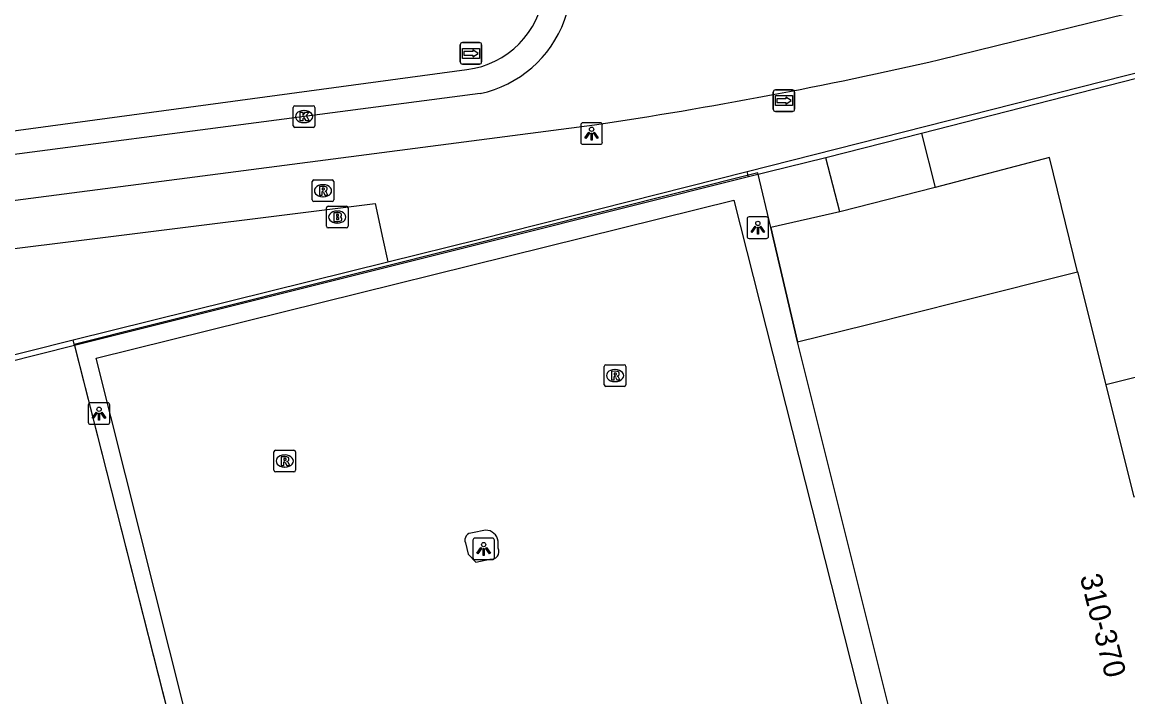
# Model space of a CAD drawing. Extents: x 160806 to 161707, y 383697 to 384148.
# Drawn here: x 160905.1 to 160956.3, y 383728.8 to 383760.1 of the extents above; entities that cross this region are included whole.
import ezdxf

# ---------------------------------------------------------------- set-up
doc = ezdxf.new("R2010")
doc.units = 0
for name, color, linetype in [('IMGEO_Brandkraan', 7, 'Continuous'), ('IMGEO_Dek', 7, 'Continuous'), ('IMGEO_Fietspad_open', 7, 'Continuous'), ('IMGEO_Kolk', 7, 'Continuous'), ('IMGEO_Lichtpunt', 7, 'Continuous'), ('IMGEO_Muur', 7, 'Continuous'), ('IMGEO_Pand', 7, 'Continuous'), ('IMGEO_Pand_nummerreeks', 7, 'Continuous'), ('IMGEO_Pand_overbouw', 7, 'Continuous'), ('IMGEO_Parkeervlak_gesloten', 7, 'Continuous'), ('IMGEO_Parkeervlak_open', 7, 'Continuous'), ('IMGEO_Rioolput', 7, 'Continuous'), ('IMGEO_Voetpad_gesloten', 7, 'Continuous'), ('IMGEO_Voetpad_open', 7, 'Continuous'), ('IMGEO_Wegwijzer', 7, 'Continuous')]:
    doc.layers.add(name, color=color, linetype=linetype)

msp = doc.modelspace()

# ---------------------------------------------------------------- linework, layer by layer
at = {"layer": 'IMGEO_Brandkraan'}
for p, q in [((160919.175, 383750.595), (160919.175, 383751.447)), ((160919.25, 383751.521), (160920.102, 383751.521)), ((160919.663, 383751.301), (160919.688, 383751.301)), ((160920.176, 383751.447), (160920.176, 383750.595)), ((160919.686, 383750.741), (160919.661, 383750.741)), ((160920.102, 383750.521), (160919.25, 383750.521))]:
    msp.add_line(p, q, dxfattribs=at)
for points in [[(160919.175, 383750.595), (160919.175, 383751.447)], [(160919.25, 383751.521), (160920.102, 383751.521)], [(160919.523, 383751.221), (160919.523, 383750.821), (160919.736, 383750.821)], [(160919.754, 383751.221), (160919.523, 383751.221)], [(160920.176, 383751.447), (160920.176, 383750.595)], [(160919.702, 383751.14), (160919.648, 383751.14), (160919.648, 383751.064)], [(160919.648, 383751.064), (160919.701, 383751.064)], [(160919.71, 383750.988), (160919.648, 383750.988), (160919.648, 383750.907)], [(160919.648, 383750.907), (160919.71, 383750.907)], [(160920.102, 383750.521), (160919.25, 383750.521)]]:
    msp.add_lwpolyline(points, dxfattribs=at)
for centre, radius, start, end in [((160919.252, 383751.445), 0.0765, 91.552, 178.448), ((160919.252, 383751.445), 0.0765, 91.552, 178.448), ((160919.758, 383751.076), 0.145, 59.4692, 91.5367), ((160919.783, 383751.123), 0.0922, 285.5137, 58.1501), ((160920.1, 383751.445), 0.0765, 1.552, 88.448), ((160920.1, 383751.445), 0.0765, 1.552, 88.448), ((160919.703, 383751.102), 0.0379, 267.8285, 90.9355), ((160919.711, 383750.947), 0.0404, 269.8759, 90.5077), ((160919.742, 383751.072), 0.251, 268.6676, 293.5347), ((160919.788, 383750.931), 0.105, 301.3115, 78.989), ((160919.252, 383750.597), 0.0765, 181.552, 268.448), ((160919.252, 383750.597), 0.0765, 181.552, 268.448), ((160920.1, 383750.597), 0.0765, 271.552, 358.448), ((160920.1, 383750.597), 0.0765, 271.552, 358.448)]:
    msp.add_arc(centre, radius, start, end, dxfattribs=at)
for centre, major_axis, ratio, start_param, end_param in [((160919.662, 383751.021), (-0.387, 0.002), 0.722429, 4.712389, 7.853982), ((160919.687, 383751.021), (-0.39, 0.002), 0.717154, 1.570796, 4.712389)]:
    msp.add_ellipse(centre, major_axis=major_axis, ratio=ratio, start_param=start_param, end_param=end_param, dxfattribs=at)
at = {"layer": 'IMGEO_Dek'}
msp.add_lwpolyline([(160965.894, 383710.159), (160949.913, 383709.678), (160949.497, 383711.315), (160949.382, 383711.774), (160941.019, 383745.231), (160939.898, 383750), (160939.772, 383750.534), (160939.177, 383753.065), (160907.479, 383745.104), (160918.048, 383703.574), (160983.268, 383705.804)], dxfattribs=at)
at = {"layer": 'IMGEO_Fietspad_open'}
for points in [[(160947.606, 383758.324), (160957.999, 383760.873), (160958.651, 383761.038), (160960.089, 383761.401), (160969.85, 383763.865), (160970.809, 383764.107), (160986.327, 383768.025), (161022.896, 383777.258), (161039.914, 383781.555), (161040.772, 383781.738)], [(160926.307, 383756.75), (160894.194, 383752.541)], [(160894.884, 383750.529), (160931.609, 383755.303)]]:
    msp.add_lwpolyline(points, dxfattribs=at)
for centre, radius, start, end in [((160925.172, 383761.997), 5.368, 282.2012, 37.6103), ((160901.535, 383958.42), 205.331, 278.42229, 282.9662)]:
    msp.add_arc(centre, radius, start, end, dxfattribs=at)
at = {"layer": 'IMGEO_Kolk'}
for p, q in [((160917.637, 383755.254), (160917.637, 383756.106)), ((160917.712, 383756.18), (160918.564, 383756.18)), ((160918.125, 383755.96), (160918.15, 383755.96)), ((160918.638, 383756.106), (160918.638, 383755.254)), ((160918.148, 383755.4), (160918.123, 383755.4)), ((160918.564, 383755.18), (160917.712, 383755.18))]:
    msp.add_line(p, q, dxfattribs=at)
for points in [[(160917.637, 383755.254), (160917.637, 383756.106)], [(160917.712, 383756.18), (160918.564, 383756.18)], [(160917.958, 383755.88), (160918.081, 383755.88), (160918.081, 383755.729), (160918.211, 383755.88), (160918.375, 383755.88), (160918.229, 383755.729), (160918.382, 383755.48), (160918.23, 383755.48), (160918.145, 383755.644), (160918.081, 383755.577), (160918.081, 383755.48), (160917.958, 383755.48), (160917.958, 383755.88)], [(160918.638, 383756.106), (160918.638, 383755.254)], [(160918.564, 383755.18), (160917.712, 383755.18)]]:
    msp.add_lwpolyline(points, dxfattribs=at)
for centre, start, end in [((160917.714, 383756.104), 91.552, 178.448), ((160917.714, 383756.104), 91.552, 178.448), ((160918.562, 383756.104), 1.552, 88.448), ((160918.562, 383756.104), 1.552, 88.448), ((160917.714, 383755.256), 181.552, 268.448), ((160917.714, 383755.256), 181.552, 268.448), ((160918.562, 383755.256), 271.552, 358.448), ((160918.562, 383755.256), 271.552, 358.448)]:
    msp.add_arc(centre, 0.0765, start, end, dxfattribs=at)
for centre, major_axis, ratio, start_param, end_param in [((160918.124, 383755.68), (-0.387, 0.002), 0.722429, 4.712389, 7.853982), ((160918.149, 383755.68), (-0.39, 0.002), 0.717154, 1.570796, 4.712389)]:
    msp.add_ellipse(centre, major_axis=major_axis, ratio=ratio, start_param=start_param, end_param=end_param, dxfattribs=at)
at = {"layer": 'IMGEO_Lichtpunt'}
for p, q in [((160930.97, 383755.297), (160930.97, 383754.49)), ((160930.97, 383755.297), (160930.97, 383754.49)), ((160931.872, 383755.392), (160931.064, 383755.392)), ((160931.872, 383755.392), (160931.064, 383755.392)), ((160931.966, 383754.49), (160931.966, 383755.297)), ((160931.966, 383754.49), (160931.966, 383755.297)), ((160931.064, 383754.396), (160931.872, 383754.396)), ((160931.064, 383754.396), (160931.872, 383754.396)), ((160938.677, 383750.931), (160938.677, 383750.124)), ((160938.677, 383750.931), (160938.677, 383750.124)), ((160939.579, 383751.026), (160938.771, 383751.026)), ((160939.579, 383751.026), (160938.771, 383751.026)), ((160939.673, 383750.124), (160939.673, 383750.931)), ((160939.673, 383750.124), (160939.673, 383750.931)), ((160938.771, 383750.03), (160939.579, 383750.03)), ((160938.771, 383750.03), (160939.579, 383750.03)), ((160908.135, 383742.312), (160908.135, 383741.505)), ((160908.135, 383742.312), (160908.135, 383741.505)), ((160909.037, 383742.407), (160908.229, 383742.407)), ((160909.037, 383742.407), (160908.229, 383742.407)), ((160909.131, 383741.505), (160909.131, 383742.312)), ((160909.131, 383741.505), (160909.131, 383742.312)), ((160908.229, 383741.411), (160909.037, 383741.411)), ((160908.229, 383741.411), (160909.037, 383741.411)), ((160925.965, 383736.034), (160925.965, 383735.227)), ((160925.965, 383736.034), (160925.965, 383735.227)), ((160926.867, 383736.129), (160926.059, 383736.129)), ((160926.867, 383736.129), (160926.059, 383736.129)), ((160926.961, 383735.227), (160926.961, 383736.034)), ((160926.961, 383735.227), (160926.961, 383736.034)), ((160926.059, 383735.133), (160926.867, 383735.133)), ((160926.059, 383735.133), (160926.867, 383735.133))]:
    msp.add_line(p, q, dxfattribs=at)
for points in [[(160931.344, 383754.961), (160931.383, 383754.933), (160931.195, 383754.671), (160931.157, 383754.698), (160931.344, 383754.961)], [(160931.446, 383754.913), (160931.493, 383754.913), (160931.493, 383754.591), (160931.446, 383754.591), (160931.446, 383754.913)], [(160931.556, 383754.933), (160931.594, 383754.96), (160931.781, 383754.698), (160931.742, 383754.67), (160931.556, 383754.933)], [(160939.051, 383750.595), (160939.09, 383750.567), (160938.902, 383750.305), (160938.864, 383750.332), (160939.051, 383750.595)], [(160939.153, 383750.547), (160939.2, 383750.547), (160939.2, 383750.225), (160939.153, 383750.225), (160939.153, 383750.547)], [(160939.263, 383750.567), (160939.301, 383750.594), (160939.488, 383750.332), (160939.449, 383750.304), (160939.263, 383750.567)], [(160908.509, 383741.976), (160908.548, 383741.948), (160908.36, 383741.686), (160908.322, 383741.713), (160908.509, 383741.976)], [(160908.721, 383741.948), (160908.759, 383741.975), (160908.946, 383741.713), (160908.907, 383741.685), (160908.721, 383741.948)], [(160908.611, 383741.928), (160908.658, 383741.928), (160908.658, 383741.606), (160908.611, 383741.606), (160908.611, 383741.928)], [(160926.339, 383735.698), (160926.378, 383735.67), (160926.19, 383735.408), (160926.152, 383735.435), (160926.339, 383735.698)], [(160926.441, 383735.65), (160926.488, 383735.65), (160926.488, 383735.328), (160926.441, 383735.328), (160926.441, 383735.65)], [(160926.551, 383735.67), (160926.589, 383735.697), (160926.776, 383735.435), (160926.737, 383735.407), (160926.551, 383735.67)]]:
    msp.add_lwpolyline(points, dxfattribs=at)
for centre in [(160931.469, 383755.095), (160939.176, 383750.729), (160908.634, 383742.11), (160926.464, 383735.832)]:
    msp.add_circle(centre, 0.0994, dxfattribs=at)
for centre, start, end in [((160931.064, 383755.297), 90, 180), ((160931.064, 383755.297), 90, 180), ((160931.872, 383755.297), 0, 90), ((160931.872, 383755.297), 0, 90), ((160931.064, 383754.49), 180, 270), ((160931.064, 383754.49), 180, 270), ((160931.872, 383754.49), 270, 0), ((160931.872, 383754.49), 270, 360), ((160938.771, 383750.931), 90, 180), ((160938.771, 383750.931), 90, 180), ((160939.579, 383750.931), 0, 90), ((160939.579, 383750.931), 0, 90), ((160938.771, 383750.124), 180, 270), ((160938.771, 383750.124), 180, 270), ((160939.579, 383750.124), 270, 0), ((160939.579, 383750.124), 270, 360), ((160908.229, 383742.312), 90, 180), ((160908.229, 383742.312), 90, 180), ((160909.037, 383742.312), 0, 90), ((160909.037, 383742.312), 0, 90), ((160908.229, 383741.505), 180, 270), ((160908.229, 383741.505), 180, 270), ((160909.037, 383741.505), 270, 0), ((160909.037, 383741.505), 270, 360), ((160926.059, 383736.034), 90, 180), ((160926.059, 383736.034), 90, 180), ((160926.867, 383736.034), 0, 90), ((160926.867, 383736.034), 0, 90), ((160926.059, 383735.227), 180, 270), ((160926.059, 383735.227), 180, 270), ((160926.867, 383735.227), 270, 0), ((160926.867, 383735.227), 270, 360)]:
    msp.add_arc(centre, 0.0946, start, end, dxfattribs=at)
at = {"layer": 'IMGEO_Muur'}
for points in [[(160938.676, 383753.139), (160959.333, 383758.368)], [(160959.333, 383758.368), (160959.395, 383758.125), (160946.757, 383754.904)], [(160942.334, 383753.775), (160938.74, 383752.883)], [(160938.74, 383752.883), (160927.222, 383750), (160907.502, 383745.064)], [(160922.028, 383748.942), (160926.276, 383750), (160938.676, 383753.139)], [(160938.74, 383752.883), (160938.676, 383753.139)], [(160907.436, 383745.322), (160922.028, 383748.942)], [(160900.906, 383743.686), (160907.436, 383745.322)], [(160907.502, 383745.064), (160901.057, 383743.443), (160900.906, 383743.686)], [(160907.502, 383745.064), (160907.436, 383745.322)]]:
    msp.add_lwpolyline(points, dxfattribs=at)
at = {"layer": 'IMGEO_Pand'}
for points in [[(160946.757, 383754.904), (160947.4, 383752.385), (160942.978, 383751.256), (160942.334, 383753.775)], [(160946.757, 383754.904), (160942.334, 383753.775)], [(160955.357, 383743.043), (160956.607, 383738.039), (160961.709, 383739.314), (160961.795, 383738.969), (160962.631, 383735.625), (160963.657, 383731.523), (160958.607, 383730.26), (160962.541, 383714.522), (160959.898, 383713.862), (160960.518, 383711.382), (160956.184, 383710.298), (160955.552, 383712.828), (160949.497, 383711.315), (160949.382, 383711.774), (160941.019, 383745.231), (160944.207, 383746.028), (160948.634, 383747.134), (160953.999, 383748.475), (160955.308, 383743.237), (160955.357, 383743.043)]]:
    msp.add_lwpolyline(points, dxfattribs=at)
at = {"layer": 'IMGEO_Pand_overbouw'}
for points in [[(160942.978, 383751.256), (160939.772, 383750.534), (160939.898, 383750), (160941.019, 383745.231), (160944.207, 383746.028), (160948.634, 383747.134), (160953.999, 383748.475), (160953.626, 383750), (160952.702, 383753.779), (160947.4, 383752.385)], [(160962.624, 383741.824), (160961.54, 383741.548), (160961.142, 383742.274), (160960.626, 383742.816), (160960.1, 383743.212), (160959.552, 383743.495), (160958.926, 383743.665), (160958.73, 383743.717), (160958.447, 383743.791), (160957.901, 383743.793), (160957.479, 383743.751), (160956.788, 383743.617), (160955.308, 383743.237), (160956.607, 383738.039), (160961.709, 383739.314), (160962.561, 383735.906), (160964.085, 383736.287)]]:
    msp.add_lwpolyline(points, close=True, dxfattribs=at)
at = {"layer": 'IMGEO_Parkeervlak_gesloten'}
for points in [[(160926.557, 383736.503), (160925.949, 383736.372)], [(160925.622, 383735.913), (160925.739, 383735.38), (160926.097, 383735.014), (160926.744, 383735.158)], [(160927.134, 383735.668), (160927.132, 383735.986)]]:
    msp.add_lwpolyline(points, dxfattribs=at)
for centre, radius, start, end in [((160925.923, 383736.045), 0.328, 85.3696, 203.6969), ((160926.547, 383735.913), 0.59, 7.0647, 89.016), ((160926.817, 383735.506), 0.356, 258.0785, 27.1108)]:
    msp.add_arc(centre, radius, start, end, dxfattribs=at)
at = {"layer": 'IMGEO_Parkeervlak_open'}
msp.add_lwpolyline([(160907.502, 383745.064), (160917.974, 383703.804)], dxfattribs=at)
at = {"layer": 'IMGEO_Rioolput'}
for p, q in [((160918.59, 383752.742), (160919.442, 383752.742)), ((160918.515, 383751.816), (160918.515, 383752.668)), ((160919.003, 383752.522), (160919.028, 383752.522)), ((160919.516, 383752.668), (160919.516, 383751.816)), ((160919.442, 383751.742), (160918.59, 383751.742)), ((160919.026, 383751.962), (160919.001, 383751.962)), ((160932.055, 383743.242), (160932.055, 383744.094)), ((160932.13, 383744.168), (160932.982, 383744.168)), ((160933.056, 383744.094), (160933.056, 383743.242)), ((160932.543, 383743.948), (160932.568, 383743.948)), ((160932.982, 383743.168), (160932.13, 383743.168)), ((160932.566, 383743.388), (160932.541, 383743.388)), ((160916.743, 383739.28), (160916.743, 383740.132)), ((160916.818, 383740.206), (160917.67, 383740.206)), ((160917.231, 383739.986), (160917.256, 383739.986)), ((160917.744, 383740.132), (160917.744, 383739.28)), ((160917.254, 383739.426), (160917.229, 383739.426)), ((160917.67, 383739.206), (160916.818, 383739.206))]:
    msp.add_line(p, q, dxfattribs=at)
for points in [[(160918.59, 383752.742), (160919.442, 383752.742)], [(160918.515, 383751.816), (160918.515, 383752.668)], [(160919.104, 383752.44), (160918.852, 383752.442), (160918.852, 383752.042)], [(160919.03, 383752.361), (160918.976, 383752.361), (160918.976, 383752.28)], [(160918.976, 383752.28), (160919.028, 383752.28)], [(160919.516, 383752.668), (160919.516, 383751.816)], [(160919.442, 383751.742), (160918.59, 383751.742)], [(160918.852, 383752.042), (160918.976, 383752.042), (160918.976, 383752.204), (160918.987, 383752.204)], [(160919.034, 383752.175), (160919.105, 383752.042), (160919.245, 383752.042), (160919.18, 383752.168)], [(160932.055, 383743.242), (160932.055, 383744.094)], [(160932.13, 383744.168), (160932.982, 383744.168)], [(160933.056, 383744.094), (160933.056, 383743.242)], [(160932.644, 383743.866), (160932.392, 383743.868), (160932.392, 383743.468)], [(160932.392, 383743.468), (160932.516, 383743.468), (160932.516, 383743.63), (160932.527, 383743.63)], [(160932.57, 383743.787), (160932.516, 383743.787), (160932.516, 383743.706)], [(160932.516, 383743.706), (160932.568, 383743.706)], [(160932.574, 383743.601), (160932.645, 383743.468), (160932.785, 383743.468), (160932.72, 383743.594)], [(160932.982, 383743.168), (160932.13, 383743.168)], [(160916.743, 383739.28), (160916.743, 383740.132)], [(160916.818, 383740.206), (160917.67, 383740.206)], [(160917.744, 383740.132), (160917.744, 383739.28)], [(160917.332, 383739.904), (160917.08, 383739.906), (160917.08, 383739.506)], [(160917.08, 383739.506), (160917.204, 383739.506), (160917.204, 383739.668), (160917.215, 383739.668)], [(160917.258, 383739.825), (160917.204, 383739.825), (160917.204, 383739.744)], [(160917.204, 383739.744), (160917.256, 383739.744)], [(160917.262, 383739.639), (160917.333, 383739.506), (160917.473, 383739.506), (160917.408, 383739.632)], [(160917.67, 383739.206), (160916.818, 383739.206)]]:
    msp.add_lwpolyline(points, dxfattribs=at)
for centre, radius, start, end in [((160918.592, 383752.666), 0.0765, 91.552, 178.448), ((160918.592, 383752.666), 0.0765, 91.552, 178.448), ((160919.44, 383752.666), 0.0765, 1.552, 88.448), ((160919.44, 383752.666), 0.0765, 1.552, 88.448), ((160919.012, 383752.469), 0.19, 274.7715, 282.9687), ((160919.036, 383752.265), 0.0964, 77.0061, 93.1865), ((160919.05, 383752.322), 0.0378, 276.6634, 79.6772), ((160919.103, 383752.33), 0.109, 350.3612, 89.416), ((160919.101, 383752.33), 0.112, 277.5842, 350.9817), ((160918.592, 383751.818), 0.0765, 181.552, 268.448), ((160918.592, 383751.818), 0.0765, 181.552, 268.448), ((160918.986, 383752.151), 0.0533, 26.0293, 88.6989), ((160919.085, 383752.115), 0.108, 29.5134, 73.7905), ((160919.44, 383751.818), 0.0765, 271.552, 358.448), ((160919.44, 383751.818), 0.0765, 271.552, 358.448), ((160932.132, 383744.092), 0.0765, 91.552, 178.448), ((160932.132, 383744.092), 0.0765, 91.552, 178.448), ((160932.98, 383744.092), 0.0765, 1.552, 88.448), ((160932.98, 383744.092), 0.0765, 1.552, 88.448), ((160932.526, 383743.577), 0.0533, 26.0293, 88.6989), ((160932.552, 383743.895), 0.19, 274.7715, 282.9687), ((160932.576, 383743.691), 0.0964, 77.0061, 93.1865), ((160932.59, 383743.748), 0.0378, 276.6634, 79.6772), ((160932.643, 383743.756), 0.109, 350.3612, 89.416), ((160932.641, 383743.756), 0.112, 277.5842, 350.9817), ((160932.625, 383743.541), 0.108, 29.5134, 73.7905), ((160932.132, 383743.244), 0.0765, 181.552, 268.448), ((160932.132, 383743.244), 0.0765, 181.552, 268.448), ((160932.98, 383743.244), 0.0765, 271.552, 358.448), ((160932.98, 383743.244), 0.0765, 271.552, 358.448), ((160916.82, 383740.13), 0.0765, 91.552, 178.448), ((160916.82, 383740.13), 0.0765, 91.552, 178.448), ((160917.668, 383740.13), 0.0765, 1.552, 88.448), ((160917.668, 383740.13), 0.0765, 1.552, 88.448), ((160917.214, 383739.615), 0.0533, 26.0293, 88.6989), ((160917.24, 383739.933), 0.19, 274.7715, 282.9687), ((160917.264, 383739.729), 0.0964, 77.0061, 93.1865), ((160917.278, 383739.786), 0.0378, 276.6634, 79.6772), ((160917.331, 383739.794), 0.109, 350.3612, 89.416), ((160917.329, 383739.794), 0.112, 277.5842, 350.9817), ((160917.313, 383739.579), 0.108, 29.5134, 73.7905), ((160916.82, 383739.282), 0.0765, 181.552, 268.448), ((160916.82, 383739.282), 0.0765, 181.552, 268.448), ((160917.668, 383739.282), 0.0765, 271.552, 358.448), ((160917.668, 383739.282), 0.0765, 271.552, 358.448)]:
    msp.add_arc(centre, radius, start, end, dxfattribs=at)
for centre, major_axis, ratio, start_param, end_param in [((160919.002, 383752.242), (-0.387, 0.002), 0.722429, 4.712389, 7.853982), ((160919.027, 383752.242), (-0.39, 0.002), 0.717154, 1.570796, 4.712389), ((160932.542, 383743.668), (-0.387, 0.002), 0.722429, 4.712389, 7.853982), ((160932.567, 383743.668), (-0.39, 0.002), 0.717154, 1.570796, 4.712389), ((160917.23, 383739.706), (-0.387, 0.002), 0.722429, 4.712389, 7.853982), ((160917.255, 383739.706), (-0.39, 0.002), 0.717154, 1.570796, 4.712389)]:
    msp.add_ellipse(centre, major_axis=major_axis, ratio=ratio, start_param=start_param, end_param=end_param, dxfattribs=at)
at = {"layer": 'IMGEO_Voetpad_gesloten'}
for points in [[(160965.894, 383710.159), (160949.913, 383709.678), (160949.497, 383711.315), (160949.382, 383711.774), (160941.019, 383745.231), (160939.898, 383750), (160939.772, 383750.534), (160939.177, 383753.065), (160907.479, 383745.104), (160918.048, 383703.574), (160983.268, 383705.804)], [(160945.346, 383704.857), (160918.679, 383703.958), (160908.505, 383744.478), (160938.057, 383751.803), (160947.996, 383712.552), (160943.296, 383711.315)]]:
    msp.add_lwpolyline(points, dxfattribs=at)
at = {"layer": 'IMGEO_Voetpad_open'}
for points in [[(160894.194, 383752.541), (160894.066, 383753.592), (160895.526, 383753.783), (160925.691, 383757.859)], [(160895.153, 383748.373), (160908.189, 383750), (160921.433, 383751.653), (160921.796, 383750), (160922.028, 383748.942)]]:
    msp.add_lwpolyline(points, dxfattribs=at)
msp.add_arc((160925.158, 383761.971), 4.146, 277.3808, 353.3024, dxfattribs=at)
at = {"layer": 'IMGEO_Wegwijzer'}
for p, q in [((160925.381, 383758.214), (160925.381, 383759.014)), ((160925.381, 383759.014), (160925.381, 383758.214)), ((160925.481, 383759.114), (160926.271, 383759.114)), ((160926.271, 383759.114), (160925.481, 383759.114)), ((160926.371, 383759.014), (160926.371, 383758.214)), ((160926.371, 383758.214), (160926.371, 383759.014)), ((160926.271, 383758.114), (160925.481, 383758.114)), ((160925.481, 383758.114), (160926.271, 383758.114)), ((160939.992, 383756.92), (160940.782, 383756.92)), ((160940.782, 383756.92), (160939.992, 383756.92)), ((160939.892, 383756.02), (160939.892, 383756.82)), ((160939.892, 383756.82), (160939.892, 383756.02)), ((160940.882, 383756.82), (160940.882, 383756.02)), ((160940.882, 383756.02), (160940.882, 383756.82)), ((160940.782, 383755.92), (160939.992, 383755.92)), ((160939.992, 383755.92), (160940.782, 383755.92))]:
    msp.add_line(p, q, dxfattribs=at)
for points in [[(160925.482, 383758.846), (160926.27, 383758.846), (160926.27, 383758.382), (160925.482, 383758.382), (160925.482, 383758.846)], [(160925.547, 383758.698), (160925.547, 383758.614), (160925.547, 383758.53), (160925.958, 383758.53), (160925.958, 383758.447), (160926.205, 383758.614), (160925.958, 383758.781), (160925.958, 383758.698), (160925.547, 383758.698)], [(160939.993, 383756.652), (160940.781, 383756.652), (160940.781, 383756.188), (160939.993, 383756.188), (160939.993, 383756.652)], [(160940.058, 383756.504), (160940.058, 383756.42), (160940.058, 383756.336), (160940.469, 383756.336), (160940.469, 383756.253), (160940.716, 383756.42), (160940.469, 383756.587), (160940.469, 383756.504), (160940.058, 383756.504)]]:
    msp.add_lwpolyline(points, dxfattribs=at)
for centre, start, end in [((160925.481, 383759.014), 90, 180), ((160925.481, 383759.014), 90, 180), ((160926.271, 383759.014), 0, 90), ((160926.271, 383759.014), 360, 90), ((160925.481, 383758.214), 180, 270), ((160925.481, 383758.214), 180, 270), ((160926.271, 383758.214), 270, 0), ((160926.271, 383758.214), 270, 0), ((160939.992, 383756.82), 90, 180), ((160939.992, 383756.82), 90, 180), ((160940.782, 383756.82), 0, 90), ((160940.782, 383756.82), 360, 90), ((160939.992, 383756.02), 180, 270), ((160939.992, 383756.02), 180, 270), ((160940.782, 383756.02), 270, 0), ((160940.782, 383756.02), 270, 0)]:
    msp.add_arc(centre, 0.1, start, end, dxfattribs=at)

# ---------------------------------------------------------------- texts
at = {"layer": 'IMGEO_Pand_nummerreeks'}
msp.add_text('310-370', height=1, rotation=284.2034, dxfattribs=at).set_placement((160954.098, 383734.342))

doc.saveas('drawing.dxf')
